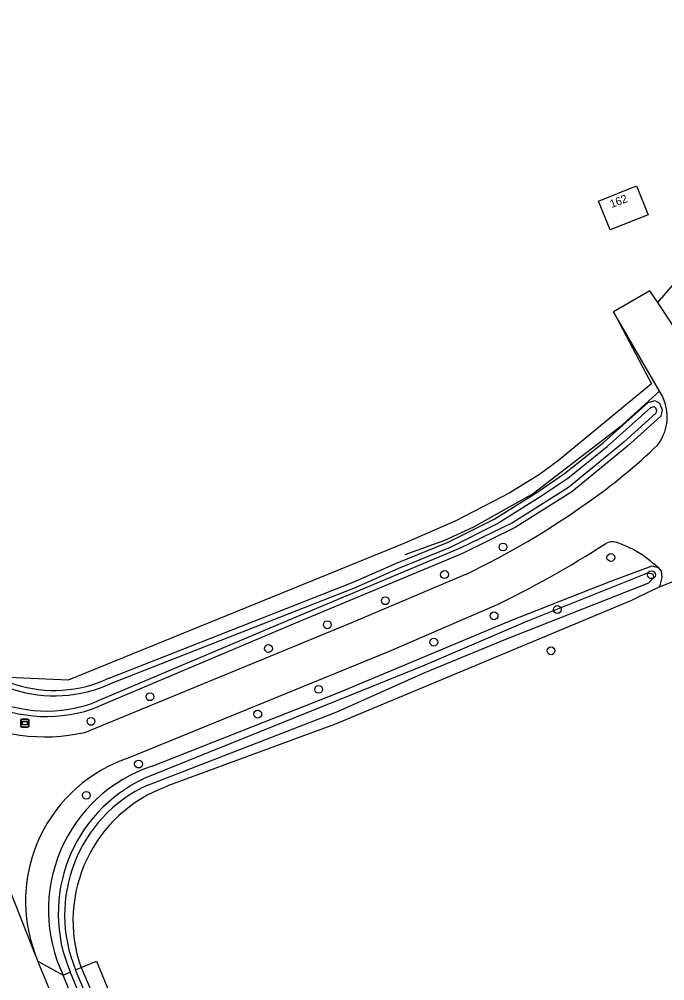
# Model space of a CAD drawing. Extents: x 156061 to 157804, y 383451 to 385640.
# Drawn here: x 157628.5 to 157709.2, y 383765.8 to 383885.9 of the extents above; entities that cross this region are included whole.
import ezdxf

# ---------------------------------------------------------------- set-up
doc = ezdxf.new("R2010")
doc.units = 0
for name, color, linetype in [('IMGEO_Boom', 7, 'Continuous'), ('IMGEO_Bouwland', 7, 'Continuous'), ('IMGEO_Gemengd_bos', 7, 'Continuous'), ('IMGEO_Groenvoorziening', 7, 'Continuous'), ('IMGEO_Hek', 7, 'Continuous'), ('IMGEO_Pand', 7, 'Continuous'), ('IMGEO_Pand_nummerreeks', 7, 'Continuous'), ('IMGEO_Rijbaan_lokaal_gesloten', 7, 'Continuous'), ('IMGEO_Straatnaambord', 7, 'Continuous'), ('IMGEO_Waterloop', 7, 'Continuous')]:
    doc.layers.add(name, color=color, linetype=linetype)

msp = doc.modelspace()

# ---------------------------------------------------------------- linework, layer by layer
at = {"layer": 'IMGEO_Boom'}
for centre in [(157688.98, 383820), (157702.46, 383818.69), (157681.67, 383816.56), (157707.54, 383816.54), (157674.27, 383813.29), (157695.76, 383812.19), (157687.86, 383811.41), (157667.02, 383810.29), (157659.66, 383807.32), (157680.33, 383808.11), (157694.97, 383807.04), (157665.93, 383802.22), (157644.85, 383801.3), (157658.32, 383799.13), (157637.48, 383798.22), (157643.42, 383792.89), (157636.9, 383788.98)]:
    msp.add_circle(centre, 0.489, dxfattribs=at)
at = {"layer": 'IMGEO_Bouwland'}
for points in [[(157708.34, 383850.55), (157711.22, 383853.86), (157713.8, 383857.36), (157714.67, 383858.73), (157717.72, 383864.02), (157719.04, 383866.63), (157723.96, 383877.57), (157725.79, 383882.93), (157727.04, 383888.46), (157727.15, 383889.11), (157732.6, 383924.65), (157744.46, 384000), (157750.58, 384037.88)], [(157702.8, 383849.36), (157707.55, 383840.38), (157700.2, 383834.34), (157695.92, 383830.81), (157693.54, 383829.05), (157691.04, 383827.5), (157689.84, 383826.75), (157683.07, 383823.26), (157676.59, 383820.43), (157634.61, 383803.39), (157626.26, 383803.73), (157620.27, 383810.26), (157611.86, 383828.59), (157592.66, 383877.06), (157588.09, 383888.13), (157579.36, 383907.86), (157571.61, 383923.12), (157569.27, 383927.73), (157568.67, 383928.38)]]:
    msp.add_lwpolyline(points, dxfattribs=at)
at = {"layer": 'IMGEO_Gemengd_bos'}
for points in [[(157708.53, 383815.04), (157705.69, 383813.65), (157705.05, 383813.33), (157667.91, 383797.83), (157663.7, 383796.28), (157646.96, 383790.11)], [(157636.23, 383767.46), (157638.16, 383768.26), (157645.65, 383750), (157659.25, 383715.79), (157661.48, 383711.42), (157662.15, 383710.22), (157663.74, 383707.57), (157665.42, 383704.98), (157667.21, 383702.45), (157669.1, 383700), (157669.46, 383699.53), (157671.5, 383697.09), (157673.62, 383694.72), (157675.84, 383692.43), (157678.13, 383690.22), (157680.51, 383688.11), (157682.97, 383686.08), (157685.5, 383684.15), (157688.1, 383682.32), (157690.77, 383680.59), (157691.82, 383679.96)]]:
    msp.add_lwpolyline(points, dxfattribs=at)
msp.add_arc((157653.06, 383773.35), 17.83, 110.0106, 199.319, dxfattribs=at)
at = {"layer": 'IMGEO_Groenvoorziening'}
for points in [[(157670.26, 383815.6), (157675.68, 383817.98), (157682.12, 383820.61), (157687.87, 383823.49), (157693.34, 383826.91), (157696.67, 383829.17), (157701.54, 383833.07), (157707.12, 383838.06), (157707.97, 383838.29), (157708.54, 383837.95), (157708.89, 383837.12), (157708.71, 383836.34), (157704.54, 383832.59), (157697.57, 383826.89), (157690.49, 383822.43), (157683.9, 383819.21), (157663.05, 383810.49), (157638.43, 383800.07)], [(157645.11, 383792.63), (157668.44, 383801.83), (157689.75, 383810.76), (157702.47, 383815.72), (157707.61, 383817.65), (157708.38, 383817.46)], [(157639.77, 383803.64), (157670.26, 383815.6)], [(157630.85, 383768.28), (157633.99, 383766.54)], [(157633.99, 383766.54), (157634.88, 383766.9)], [(157635.56, 383767.18), (157636.23, 383767.46)], [(157636.23, 383767.46), (157653.28, 383727.67)], [(157648.99, 383729.47), (157633.99, 383766.54)]]:
    msp.add_lwpolyline(points, dxfattribs=at)
for centre, radius, start, end in [((157631.93, 383816.45), 17.62, 195.1042, 291.6566), ((157632.86, 383818.21), 16.12, 209.8146, 295.3922), ((157651.1, 383774.67), 18.94, 108.4374, 205.4121)]:
    msp.add_arc(centre, radius, start, end, dxfattribs=at)
at = {"layer": 'IMGEO_Hek'}
msp.add_lwpolyline([(157708.52, 383839.48), (157703.56, 383834.99), (157692.77, 383826.67), (157685.27, 383822.48), (157681.68, 383820.81), (157676.7, 383819.01)], dxfattribs=at)
at = {"layer": 'IMGEO_Pand'}
msp.add_lwpolyline([(157705.68, 383865.1), (157707.12, 383861.49), (157702.37, 383859.6), (157700.93, 383863.21), (157705.68, 383865.1)], dxfattribs=at)
at = {"layer": 'IMGEO_Rijbaan_lokaal_gesloten'}
for points in [[(157708.34, 383850.55), (157707.35, 383851.98), (157702.8, 383849.36)], [(157712.55, 383844.18), (157708.34, 383850.55)], [(157709.13, 383838.3), (157708.9, 383838.83), (157708.52, 383839.48), (157702.8, 383849.36)], [(157708.38, 383817.46), (157707.84, 383817.88)], [(157708.38, 383817.46), (157708.74, 383816.97), (157708.85, 383816.19), (157708.53, 383815.04)], [(157708.53, 383815.04), (157710.52, 383815.81), (157714.13, 383817.93)], [(157636.72, 383796.85), (157670.3, 383810.66), (157684.33, 383816.59)], [(157687.73, 383812.56), (157674.73, 383806.95), (157642.21, 383793.67)], [(157630.57, 383768.98), (157630.54, 383769.04), (157617.19, 383802.77)], [(157630.85, 383768.28), (157630.57, 383768.98)], [(157661.54, 383699.39), (157657.72, 383705.7), (157654.79, 383711.05), (157649.6, 383721.99), (157638.25, 383750), (157631.95, 383765.56), (157630.85, 383768.28)]]:
    msp.add_lwpolyline(points, dxfattribs=at)
for centre, radius, start, end in [((157703.69, 383836.27), 5.81, 322.9144, 20.5475), ((157658.47, 383884.6), 71.92, 304.7814, 313.8821), ((157639.49, 383909.94), 103.57, 295.653, 305.4074), ((157702.68, 383818.67), 1.98, 60.4423, 116.0882), ((157632.26, 383928.07), 128.14, 295.6506, 302.8743), ((157699.36, 383808.51), 12.63, 47.8516, 70.1081), ((157631.68, 383819.17), 22.88, 242.0169, 282.711), ((157648.18, 383775.76), 18.88, 108.4413, 201.0517)]:
    msp.add_arc(centre, radius, start, end, dxfattribs=at)
at = {"layer": 'IMGEO_Straatnaambord'}
for p, q in [((157628.7, 383797.6), (157628.7, 383798.4)), ((157628.7, 383798.4), (157628.7, 383797.6)), ((157628.8, 383798.5), (157629.59, 383798.5)), ((157629.59, 383798.5), (157628.8, 383798.5)), ((157629.69, 383798.4), (157629.69, 383797.6)), ((157629.69, 383797.6), (157629.69, 383798.4)), ((157629.59, 383797.5), (157628.8, 383797.5)), ((157628.8, 383797.5), (157629.59, 383797.5))]:
    msp.add_line(p, q, dxfattribs=at)
for points in [[(157628.8, 383798.23), (157629.59, 383798.23), (157629.59, 383797.77), (157628.8, 383797.77), (157628.8, 383798.23)], [(157628.87, 383798.17), (157628.87, 383797.83), (157629.53, 383797.83), (157629.53, 383798.17), (157628.87, 383798.17)]]:
    msp.add_lwpolyline(points, dxfattribs=at)
for centre, start, end in [((157628.8, 383798.4), 90, 180), ((157628.8, 383798.4), 90, 180), ((157629.59, 383798.4), 0, 90), ((157629.59, 383798.4), 360, 90), ((157628.8, 383797.6), 180, 270), ((157628.8, 383797.6), 180, 270), ((157629.59, 383797.6), 270, 0), ((157629.59, 383797.6), 270, 0)]:
    msp.add_arc(centre, 0.1, start, end, dxfattribs=at)
at = {"layer": 'IMGEO_Waterloop'}
for points in [[(157640.04, 383803.01), (157670.52, 383814.96), (157675.95, 383817.35), (157682.4, 383819.98), (157688.21, 383822.89), (157693.71, 383826.34), (157697.08, 383828.62), (157701.98, 383832.54), (157707.46, 383837.44), (157707.87, 383837.55), (157707.99, 383837.47), (157708.17, 383837.06), (157708.09, 383836.71), (157704.09, 383833.11), (157697.17, 383827.45), (157690.15, 383823.04), (157683.62, 383819.84), (157662.79, 383811.12), (157638.17, 383800.71)], [(157644.57, 383790.27), (157668.12, 383799.38), (157679.12, 383804.3), (157689.35, 383808.49), (157707.19, 383815.51), (157707.82, 383816.22), (157707.73, 383816.63), (157707.04, 383816.74), (157692.02, 383810.75), (157678.92, 383805.11), (157668.31, 383800.85), (157644.21, 383791.11)], [(157634.87, 383766.92), (157634.88, 383766.9)], [(157634.88, 383766.9), (157648.74, 383733.2)], [(157657.62, 383714.79), (157635.56, 383767.18)]]:
    msp.add_lwpolyline(points, dxfattribs=at)
for centre, radius, start, end in [((157631.93, 383816.45), 16.94, 194.9621, 291.6304), ((157632.87, 383818.26), 16.85, 209.814, 295.1912), ((157652, 383774.21), 18.61, 114.74, 203.0521), ((157652.02, 383774.06), 17.84, 114.676, 202.6782)]:
    msp.add_arc(centre, radius, start, end, dxfattribs=at)

# ---------------------------------------------------------------- texts
at = {"layer": 'IMGEO_Pand_nummerreeks'}
msp.add_text('162', height=1, rotation=20.5292, dxfattribs=at).set_placement((157702.55, 383862.34))

doc.saveas('drawing.dxf')
